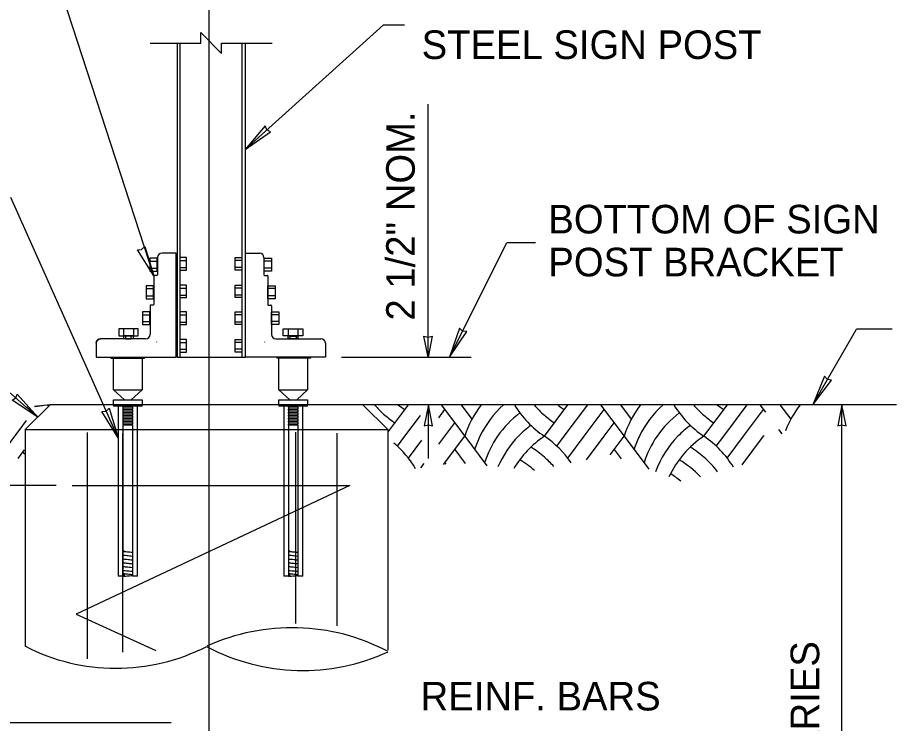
# Model space of a CAD drawing. Extents: x 99862 to 103151, y 102600 to 104676.
# Drawn here: x 100237.1 to 100728.9, y 103776.3 to 104171.1 of the extents above; entities that cross this region are included whole.
import ezdxf

# ---------------------------------------------------------------- set-up
doc = ezdxf.new("R2010")
doc.units = 0
for name, color, linetype in [('Level 1', 7, 'Continuous'), ('Level 10', 7, 'Continuous'), ('Level 15', 7, 'Continuous'), ('Level 2', 7, 'Continuous'), ('Level 20', 7, 'Continuous'), ('Level 5', 7, 'Continuous'), ('Level 6', 7, 'Continuous')]:
    doc.layers.add(name, color=color, linetype=linetype)

msp = doc.modelspace()

# ---------------------------------------------------------------- linework, layer by layer
at = {"layer": 'Level 1'}
for p, q in [((100241.42, 103940.62), (100255.34, 103954.53)), ((100444.29, 103940.62), (100430.37, 103954.53)), ((100241.42, 103940.62), (100444.29, 103940.62))]:
    msp.add_line(p, q, dxfattribs=at)
for points in [[(100430.37, 103954.53), (100255.34, 103954.53)], [(100241.42, 103940.62), (100241.42, 103819.28)], [(100444.29, 103940.62), (100444.29, 103817.34)]]:
    msp.add_lwpolyline(points, dxfattribs=at)
for centre, start, end in [((100390.7, 103714.83), 62.311, 114.5007), ((100396.71, 103920.95), 242.311, 294.5007)]:
    msp.add_arc(centre, 115.01, start, end, dxfattribs=at)
msp.add_ellipse((100294.41, 103921.53), major_axis=(-53.44, -101.84), ratio=0.974778, start_param=0.004573, end_param=0.939153, dxfattribs=at)
at = {"layer": 'Level 10'}
for p, q in [((100276.09, 103938.97), (100276.09, 103812.43)), ((100295.87, 103938.4), (100295.87, 103816.15)), ((100344.39, 103820.92), (100344.39, 103938.75)), ((100392.83, 103832.19), (100392.83, 103939.25)), ((100416.02, 103830.84), (100416.02, 103938.59)), ((100267.68, 103909.42), (100423.11, 103909.42)), ((100423.11, 103909.42), (100269.83, 103837.34)), ((100269.83, 103837.34), (100314.4, 103817.19))]:
    msp.add_line(p, q, dxfattribs=at)
at = {"layer": 'Level 15'}
for p, q in [((100313.33, 104026.58), (100239.9, 104252.06)), ((100344.07, 104241.59), (100344.07, 103359.1)), ((100364.36, 104097.36), (100441.61, 104166.9)), ((100453.62, 104166.9), (100441.61, 104166.9)), ((100293.37, 103936.03), (100233.37, 104070.54)), ((100478.83, 103981.12), (100510.95, 104045.18)), ((100526.97, 104045.18), (100510.95, 104045.18)), ((100682.09, 103954.53), (100706.5, 103996.8)), ((100726.5, 103996.8), (100706.5, 103996.8)), ((100241.92, 103953.22), (100196.88, 103992.57)), ((100418.34, 103981.12), (100490.84, 103981.12)), ((100241.93, 103953.21), (100241.92, 103953.22)), ((100242.09, 103953.06), (100241.93, 103953.21)), ((100242.23, 103952.94), (100242.09, 103953.06)), ((100248.38, 103947.57), (100242.23, 103952.94))]:
    msp.add_line(p, q, dxfattribs=at)
for points in [[(100311.29, 104156.86), (100339.62, 104156.86), (100339.62, 104162.67), (100351.26, 104151.04), (100351.26, 104156.86), (100379.59, 104156.86)], [(100466.81, 103981.12), (100466.81, 104122.66)], [(100466.97, 103924.44), (100466.97, 103954.53)], [(100698.43, 103391.74), (100698.43, 103954.53)], [(100258.67, 103909.42), (100099.21, 103909.42)], [(100201.02, 103776.83), (100322.97, 103776.83)]]:
    msp.add_lwpolyline(points, dxfattribs=at)
for points in [[(100364.36, 104097.36), (100378.6, 104107.17), (100376.51, 104108.3), (100375.6, 104110.5)], [(100313.33, 104026.58), (100304.14, 104041.23), (100306.51, 104041.44), (100308.22, 104043.1)], [(100478.83, 103981.12), (100488.47, 103995.47), (100486.11, 103995.76), (100484.46, 103997.47)], [(100466.81, 103981.12), (100464.49, 103992.93), (100466.81, 103992.38), (100469.13, 103992.93)], [(100682.09, 103954.53), (100692.61, 103968.25), (100690.27, 103968.69), (100688.72, 103970.5)], [(100248.38, 103947.57), (100233.99, 103957.17), (100236.07, 103958.33), (100236.94, 103960.54)], [(100293.37, 103936.03), (100284.31, 103950.76), (100286.68, 103950.95), (100288.4, 103952.59)], [(100466.97, 103954.53), (100464.65, 103942.72), (100466.97, 103943.26), (100469.29, 103942.72)], [(100698.43, 103954.53), (100696.12, 103942.72), (100698.43, 103943.26), (100700.75, 103942.72)]]:
    msp.add_lwpolyline(points, close=True, dxfattribs=at)
at = {"layer": 'Level 2'}
for p, q in [((100327.93, 104156.86), (100327.93, 103981.12)), ((100290.77, 103962.95), (100290.77, 103981.12)), ((100306.83, 103981.12), (100306.83, 103962.95)), ((100383.36, 103962.95), (100383.36, 103981.12)), ((100399.42, 103981.12), (100399.42, 103962.95)), ((100290.78, 103954.47), (100290.78, 103953.68)), ((100306.74, 103954.47), (100290.78, 103954.47)), ((100306.74, 103953.68), (100290.78, 103953.68)), ((100293.41, 103953.68), (100293.41, 103858.72)), ((100296.18, 103953.28), (100296.18, 103953.68)), ((100301.34, 103953.28), (100296.18, 103953.28)), ((100301.34, 103952), (100296.18, 103952)), ((100296.18, 103951.6), (100296.18, 103952)), ((100301.34, 103951.6), (100296.18, 103951.6)), ((100301.34, 103950.32), (100296.18, 103950.32)), ((100296.18, 103949.92), (100296.18, 103950.32)), ((100296.21, 103952), (100296.21, 103953.28)), ((100296.21, 103950.32), (100296.21, 103951.6)), ((100301.31, 103953.28), (100301.31, 103952)), ((100301.31, 103951.6), (100301.31, 103950.32)), ((100301.34, 103953.28), (100301.34, 103953.68)), ((100301.34, 103951.6), (100301.34, 103952)), ((100301.34, 103949.92), (100301.34, 103950.32)), ((100304.11, 103858.72), (100304.11, 103953.68)), ((100306.74, 103953.68), (100306.74, 103954.47)), ((100383.37, 103954.47), (100383.37, 103953.68)), ((100399.33, 103954.47), (100383.37, 103954.47)), ((100399.33, 103953.68), (100383.37, 103953.68)), ((100386, 103953.68), (100386, 103858.72)), ((100388.77, 103953.28), (100388.77, 103953.68)), ((100393.93, 103953.28), (100388.77, 103953.28)), ((100393.93, 103952), (100388.77, 103952)), ((100388.77, 103951.6), (100388.77, 103952)), ((100393.93, 103951.6), (100388.77, 103951.6)), ((100393.93, 103950.32), (100388.77, 103950.32)), ((100388.77, 103949.92), (100388.77, 103950.32)), ((100388.8, 103952), (100388.8, 103953.28)), ((100388.8, 103950.32), (100388.8, 103951.6)), ((100393.9, 103953.28), (100393.9, 103952)), ((100393.9, 103951.6), (100393.9, 103950.32)), ((100393.93, 103953.28), (100393.93, 103953.68)), ((100393.93, 103951.6), (100393.93, 103952)), ((100393.93, 103949.92), (100393.93, 103950.32)), ((100396.7, 103858.72), (100396.7, 103953.68)), ((100399.33, 103953.68), (100399.33, 103954.47)), ((100301.34, 103949.92), (100296.18, 103949.92)), ((100301.34, 103948.65), (100296.18, 103948.65)), ((100296.18, 103948.24), (100296.18, 103948.65)), ((100301.34, 103948.24), (100296.18, 103948.24)), ((100301.34, 103946.97), (100296.18, 103946.97)), ((100296.18, 103946.57), (100296.18, 103946.97)), ((100301.34, 103946.57), (100296.18, 103946.57)), ((100296.21, 103948.65), (100296.21, 103949.92)), ((100296.21, 103946.97), (100296.21, 103948.24)), ((100296.21, 103945.29), (100296.21, 103946.57)), ((100301.31, 103949.92), (100301.31, 103948.65)), ((100301.31, 103948.24), (100301.31, 103946.97)), ((100301.31, 103946.57), (100301.31, 103945.29)), ((100301.34, 103948.24), (100301.34, 103948.65)), ((100301.34, 103946.57), (100301.34, 103946.97)), ((100393.93, 103949.92), (100388.77, 103949.92)), ((100393.93, 103948.65), (100388.77, 103948.65)), ((100388.77, 103948.24), (100388.77, 103948.65)), ((100393.93, 103948.24), (100388.77, 103948.24)), ((100393.93, 103946.97), (100388.77, 103946.97)), ((100388.77, 103946.57), (100388.77, 103946.97)), ((100393.93, 103946.57), (100388.77, 103946.57)), ((100388.8, 103948.65), (100388.8, 103949.92)), ((100388.8, 103946.97), (100388.8, 103948.24)), ((100388.8, 103945.29), (100388.8, 103946.57)), ((100393.9, 103949.92), (100393.9, 103948.65)), ((100393.9, 103948.24), (100393.9, 103946.97)), ((100393.9, 103946.57), (100393.9, 103945.29)), ((100393.93, 103948.24), (100393.93, 103948.65)), ((100393.93, 103946.57), (100393.93, 103946.97)), ((100301.34, 103945.29), (100296.18, 103945.29)), ((100296.18, 103944.89), (100296.18, 103945.29)), ((100301.34, 103944.89), (100296.18, 103944.89)), ((100301.34, 103943.61), (100296.18, 103943.61)), ((100296.18, 103943.21), (100296.18, 103943.61)), ((100301.34, 103943.21), (100296.18, 103943.21)), ((100296.21, 103943.61), (100296.21, 103944.89)), ((100296.21, 103858.72), (100296.21, 103943.21)), ((100301.31, 103944.89), (100301.31, 103943.61)), ((100301.31, 103943.21), (100301.31, 103858.72)), ((100301.34, 103944.89), (100301.34, 103945.29)), ((100301.34, 103943.21), (100301.34, 103943.61)), ((100393.93, 103945.29), (100388.77, 103945.29)), ((100388.77, 103944.89), (100388.77, 103945.29)), ((100393.93, 103944.89), (100388.77, 103944.89)), ((100393.93, 103943.61), (100388.77, 103943.61)), ((100388.77, 103943.21), (100388.77, 103943.61)), ((100393.93, 103943.21), (100388.77, 103943.21)), ((100388.8, 103943.61), (100388.8, 103944.89)), ((100388.8, 103858.72), (100388.8, 103943.21)), ((100393.9, 103944.89), (100393.9, 103943.61)), ((100393.9, 103943.21), (100393.9, 103858.72)), ((100393.93, 103944.89), (100393.93, 103945.29)), ((100393.93, 103943.21), (100393.93, 103943.61)), ((100293.82, 103858.72), (100293.41, 103858.72)), ((100296.21, 103858.72), (100293.82, 103858.72)), ((100303.7, 103858.72), (100301.31, 103858.72)), ((100304.11, 103858.72), (100303.7, 103858.72)), ((100386.41, 103858.72), (100386, 103858.72)), ((100388.8, 103858.72), (100386.41, 103858.72)), ((100396.29, 103858.72), (100393.9, 103858.72)), ((100396.7, 103858.72), (100396.29, 103858.72))]:
    msp.add_line(p, q, dxfattribs=at)
for points in [[(100326.31, 103981.12), (100364.57, 103981.12), (100364.57, 104156.86)], [(100326.31, 104156.86), (100326.31, 103981.12)], [(100362.86, 103981.12), (100362.86, 104156.86)], [(100311.13, 104034.91), (100315.23, 104034.91)], [(100327.87, 104035.24), (100331.63, 104035.24)], [(100362.52, 104035.24), (100358.76, 104035.24)], [(100379.26, 104034.91), (100375.16, 104034.91)], [(100311.13, 104030.89), (100315.23, 104030.89)], [(100327.87, 104031.23), (100331.63, 104031.23)], [(100362.52, 104031.23), (100358.76, 104031.23)], [(100379.26, 104030.89), (100375.16, 104030.89)], [(100309.13, 104019.48), (100313.23, 104019.48)], [(100327.87, 104019.81), (100331.63, 104019.81)], [(100362.52, 104019.81), (100358.76, 104019.81)], [(100381.27, 104019.48), (100377.17, 104019.48)], [(100309.13, 104015.46), (100313.23, 104015.46)], [(100327.87, 104015.8), (100331.63, 104015.8)], [(100362.52, 104015.8), (100358.76, 104015.8)], [(100381.27, 104015.46), (100377.17, 104015.46)], [(100307.07, 104004.79), (100311.17, 104004.79)], [(100327.87, 104004.79), (100331.63, 104004.79)], [(100362.52, 104004.79), (100358.76, 104004.79)], [(100383.33, 104004.79), (100379.23, 104004.79)], [(100307.07, 104001.11), (100311.17, 104001.11)], [(100327.87, 104000.77), (100331.63, 104000.77)], [(100362.52, 104000.77), (100358.76, 104000.77)], [(100383.33, 104001.11), (100379.23, 104001.11)], [(100296.44, 103996.96), (100296.44, 103993.09)], [(100301.91, 103996.96), (100301.91, 103993.09)], [(100388.49, 103996.96), (100388.49, 103993.09)], [(100393.95, 103996.96), (100393.95, 103993.09)], [(100300.68, 103991.55), (100301.91, 103991.55), (100301.91, 103993.09), (100296.44, 103993.09), (100296.44, 103991.55), (100297.45, 103991.55)], [(100389.71, 103991.55), (100388.49, 103991.55), (100388.49, 103993.09), (100393.96, 103993.09), (100393.96, 103991.55), (100392.95, 103991.55)], [(100327.87, 103989.35), (100331.63, 103989.35)], [(100327.87, 103985.67), (100331.63, 103985.67)], [(100362.52, 103989.35), (100358.76, 103989.35)], [(100362.52, 103985.67), (100358.76, 103985.67)], [(100296.91, 103957.26), (100290.77, 103962.95), (100306.83, 103962.95), (100300.7, 103957.26)], [(100389.49, 103957.26), (100383.36, 103962.95), (100399.42, 103962.95), (100393.29, 103957.26)]]:
    msp.add_lwpolyline(points, dxfattribs=at)
for points in [[(100315.23, 104036.58), (100311.13, 104036.58), (100311.13, 104029.22), (100315.23, 104029.22)], [(100331.63, 104036.91), (100327.87, 104036.91), (100327.87, 104029.89), (100331.63, 104029.89)], [(100358.76, 104036.91), (100362.52, 104036.91), (100362.52, 104029.89), (100358.76, 104029.89)], [(100375.16, 104036.58), (100379.26, 104036.58), (100379.26, 104029.22), (100375.16, 104029.22)], [(100313.23, 104021.15), (100309.13, 104021.15), (100309.13, 104013.79), (100313.23, 104013.79)], [(100331.63, 104021.48), (100327.87, 104021.48), (100327.87, 104014.46), (100331.63, 104014.46)], [(100358.76, 104021.48), (100362.52, 104021.48), (100362.52, 104014.46), (100358.76, 104014.46)], [(100377.17, 104021.15), (100381.27, 104021.15), (100381.27, 104013.79), (100377.17, 104013.79)], [(100311.17, 104006.46), (100307.07, 104006.46), (100307.07, 103999.43), (100311.17, 103999.43)], [(100331.63, 104006.46), (100327.87, 104006.46), (100327.87, 103999.43), (100331.63, 103999.43)], [(100358.76, 104006.46), (100362.52, 104006.46), (100362.52, 103999.43), (100358.76, 103999.43)], [(100379.23, 104006.46), (100383.33, 104006.46), (100383.33, 103999.43), (100379.23, 103999.43)], [(100304.64, 103996.96), (100293.71, 103996.96), (100293.71, 103993.09), (100304.64, 103993.09)], [(100385.76, 103996.96), (100396.69, 103996.96), (100396.69, 103993.09), (100385.76, 103993.09)], [(100300.68, 103993), (100297.45, 103993), (100297.45, 103991.46), (100300.68, 103991.46)], [(100331.63, 103991.02), (100327.87, 103991.02), (100327.87, 103984), (100331.63, 103984)], [(100358.76, 103991.02), (100362.52, 103991.02), (100362.52, 103984), (100358.76, 103984)], [(100389.71, 103993), (100392.95, 103993), (100392.95, 103991.46), (100389.71, 103991.46)], [(100308.13, 103981), (100289.31, 103981), (100289.31, 103980.58), (100308.13, 103980.58)], [(100382.27, 103981), (100401.08, 103981), (100401.08, 103980.58), (100382.27, 103980.58)], [(100290.77, 103957.26), (100306.83, 103957.26), (100306.83, 103954.59), (100290.77, 103954.59)], [(100383.36, 103957.26), (100399.42, 103957.26), (100399.42, 103954.59), (100383.36, 103954.59)]]:
    msp.add_lwpolyline(points, close=True, dxfattribs=at)
for centre, ratio, start_param, end_param in [((100296.32, 103872.13), 0.703573, 1.740072, 3.144905), ((100388.91, 103872.13), 0.703573, 1.740072, 3.144905), ((100296.32, 103859.36), 0.703842, 5.555756, 6.285821), ((100296.32, 103859.36), 0.703842, 1.475078, 3.14378), ((100296.32, 103859.36), 0.703842, 0.002636, 1.475078), ((100388.91, 103859.36), 0.703842, 5.555756, 6.285821), ((100388.91, 103859.36), 0.703842, 1.475078, 3.14378), ((100388.91, 103859.36), 0.703842, 0.002636, 1.475078)]:
    msp.add_ellipse(centre, major_axis=(0.108, -0.791), ratio=ratio, start_param=start_param, end_param=end_param, dxfattribs=at)
for points, degree in [([(100296.21, 103872.92), (100296.21, 103872.92), (100296.21, 103872.92), (100296.21, 103872.92)], 2), ([(100301.31, 103871.85), (100300.39, 103871.98), (100298.28, 103872.17), (100296.59, 103872.36), (100296.21, 103872.41)], 3), ([(100388.8, 103872.92), (100388.8, 103872.92), (100388.8, 103872.92), (100388.8, 103872.92)], 2), ([(100393.9, 103871.85), (100392.98, 103871.98), (100390.87, 103872.17), (100389.18, 103872.36), (100388.8, 103872.41)], 3), ([(100301.31, 103869.73), (100300.19, 103869.89), (100298.02, 103870.06), (100296.57, 103870.25), (100296.33, 103870.29), (100296.21, 103870.31)], 3), ([(100301.31, 103867.61), (100300.91, 103867.66), (100299.19, 103867.83), (100296.97, 103868.06), (100296.21, 103868.16)], 3), ([(100393.9, 103869.73), (100392.78, 103869.89), (100390.61, 103870.06), (100389.16, 103870.25), (100388.92, 103870.29), (100388.8, 103870.31)], 3), ([(100393.9, 103867.61), (100393.5, 103867.66), (100391.78, 103867.83), (100389.56, 103868.06), (100388.8, 103868.16)], 3), ([(100301.31, 103865.47), (100301.24, 103865.48), (100299.87, 103865.67), (100297.37, 103865.86), (100296.26, 103866.04), (100296.21, 103866.05)], 3), ([(100301.31, 103863.35), (100300.18, 103863.5), (100297.91, 103863.69), (100296.46, 103863.88), (100296.21, 103863.92)], 3), ([(100301.31, 103861.21), (100300.09, 103861.38), (100297.67, 103861.58), (100296.37, 103861.76), (100296.23, 103861.78), (100296.21, 103861.79)], 3), ([(100393.9, 103865.47), (100393.83, 103865.48), (100392.46, 103865.67), (100389.95, 103865.86), (100388.85, 103866.04), (100388.8, 103866.05)], 3), ([(100393.9, 103863.35), (100392.77, 103863.5), (100390.5, 103863.69), (100389.05, 103863.88), (100388.8, 103863.92)], 3), ([(100393.9, 103861.21), (100392.68, 103861.38), (100390.25, 103861.58), (100388.96, 103861.76), (100388.82, 103861.78), (100388.8, 103861.79)], 3), ([(100296.21, 103860.18), (100296.34, 103860.16), (100296.6, 103860.13), (100297.78, 103859.96), (100299.41, 103859.84), (100300.66, 103859.68), (100301.05, 103859.63), (100301.25, 103859.6), (100301.31, 103859.59)], 3), ([(100296.43, 103858.57), (100296.53, 103858.58), (100296.72, 103858.61), (100298.23, 103858.78), (100300.15, 103858.94), (100301.31, 103859.09)], 3), ([(100388.8, 103860.18), (100388.93, 103860.16), (100389.19, 103860.13), (100390.36, 103859.96), (100392, 103859.84), (100393.25, 103859.68), (100393.64, 103859.63), (100393.84, 103859.6), (100393.9, 103859.59)], 3), ([(100389.01, 103858.57), (100389.11, 103858.58), (100389.31, 103858.61), (100390.82, 103858.78), (100392.73, 103858.94), (100393.9, 103859.09)], 3)]:
    msp.add_open_spline(points, degree=degree, dxfattribs=at)
at = {"layer": 'Level 5'}
for p, q in [((100255.34, 103954.53), (100246.53, 103953.56)), ((100246.69, 103953.57), (100250.94, 103954.04)), ((100253.75, 103954.35), (100254.35, 103953.54)), ((100444.72, 103939.67), (100455.87, 103954.53)), ((100472.74, 103947.29), (100476.15, 103951.82)), ((100474.12, 103954.53), (100487.3, 103936.95)), ((100485.27, 103954.53), (100491.32, 103946.47)), ((100496.42, 103954.53), (100496.49, 103954.44)), ((100531.91, 103936.95), (100545.09, 103954.53)), ((100543.06, 103936.95), (100556.24, 103954.53)), ((100554.21, 103936.95), (100565.36, 103951.82)), ((100563.34, 103954.53), (100576.52, 103936.95)), ((100574.49, 103954.53), (100580.53, 103946.47)), ((100585.64, 103954.53), (100585.71, 103954.44)), ((100621.13, 103936.95), (100634.31, 103954.53)), ((100632.28, 103936.95), (100645.46, 103954.53)), ((100643.43, 103936.95), (100654.58, 103951.82)), ((100652.56, 103954.53), (100655.65, 103950.4)), ((100663.71, 103954.53), (100669.75, 103946.47)), ((100674.86, 103954.53), (100674.93, 103954.44)), ((100240.05, 103942.88), (100242.15, 103945.68)), ((100453.84, 103936.95), (100462.48, 103948.47)), ((100228.63, 103927.65), (100240.05, 103942.88)), ((100476.15, 103936.95), (100481.72, 103944.39)), ((100565.36, 103936.95), (100570.94, 103944.39)), ((100662.89, 103940.75), (100664.75, 103938.26)), ((100449.68, 103931.4), (100453.84, 103936.95)), ((100472.79, 103932.48), (100476.15, 103936.95)), ((100475.43, 103921.12), (100487.3, 103936.95)), ((100487.3, 103936.95), (100499.68, 103920.45)), ((100538.9, 103931.4), (100543.06, 103936.95)), ((100545.02, 103924.7), (100554.21, 103936.95)), ((100555.52, 103923.83), (100565.36, 103936.95)), ((100568.7, 103926.54), (100576.52, 103936.95)), ((100576.52, 103936.95), (100590.37, 103918.48)), ((100628.12, 103931.4), (100632.28, 103936.95)), ((100634.24, 103924.7), (100643.43, 103936.95)), ((100642.64, 103921.03), (100654.58, 103936.95)), ((100654.58, 103936.95), (100654.84, 103937.29)), ((100455.8, 103924.7), (100463.4, 103934.82)), ((100237.36, 103924.43), (100240.98, 103929.25)), ((100240.05, 103928.01), (100240.89, 103926.89)), ((100481.72, 103929.52), (100487.55, 103921.74)), ((100570.94, 103929.52), (100574.91, 103924.23)), ((100462.83, 103919.2), (100464.68, 103921.66)), ((100476.15, 103922.08), (100476.72, 103921.32))]:
    msp.add_line(p, q, dxfattribs=at)
msp.add_lwpolyline([(100728.92, 103954.53), (100430.37, 103954.53)], dxfattribs=at)
for centre, start, end in [((100479.75, 103991.23), 220.5665, 228.9599), ((100485.33, 103998.67), 231.4488, 236.0964), ((100541.09, 103919.84), 142.0873, 162.3566), ((100546.66, 103912.41), 131.7393, 154.2266), ((100563.39, 103983.8), 211.239, 236.0964), ((100568.97, 103991.23), 220.5665, 228.9599), ((100574.54, 103998.67), 231.4488, 236.0964), ((100630.31, 103919.84), 142.0873, 162.3566), ((100635.88, 103912.41), 131.7393, 154.2266), ((100652.61, 103983.8), 211.239, 236.0964), ((100658.19, 103991.23), 220.5665, 228.9599), ((100663.76, 103998.67), 231.4488, 236.0964), ((100719.53, 103919.84), 142.0873, 159.0693), ((100479.75, 103991.23), 228.9599, 236.0964), ((100552.24, 103904.97), 127.1006, 145.4911), ((100568.97, 103991.23), 228.9599, 236.0964), ((100641.46, 103904.97), 127.1006, 145.4911), ((100658.19, 103991.23), 228.9599, 236.0964), ((100557.82, 103897.54), 126.331, 135.7128), ((100647.04, 103897.54), 126.331, 135.7128), ((100546.66, 103912.41), 154.2265, 162.3566), ((100552.24, 103904.97), 145.491, 162.3566), ((100557.82, 103897.54), 135.7127, 156.7978), ((100563.39, 103890.1), 123.9036, 149.4093), ((100500.42, 103890.1), 34.4434, 56.0963), ((100635.88, 103912.41), 154.2265, 162.3566), ((100641.46, 103904.97), 145.491, 162.3566), ((100647.04, 103897.54), 135.7127, 159.729), ((100652.61, 103890.1), 123.9036, 154.6223), ((100589.64, 103890.1), 31.526, 56.0963), ((100411.2, 103890.1), 30.4844, 49.6595), ((100494.85, 103882.67), 48.9597, 58.5465), ((100584.07, 103882.67), 48.9597, 58.5465), ((100489.27, 103875.23), 48.8121, 59.3021), ((100494.85, 103882.67), 41.3709, 48.9597), ((100578.49, 103875.23), 43.7622, 59.3021), ((100584.07, 103882.67), 37.5154, 48.9597), ((100572.91, 103867.8), 51.2805, 58.4874)]:
    msp.add_arc(centre, 56.44, start, end, dxfattribs=at)
at = {"layer": 'Level 6'}
for p, q in [((100315.41, 104036.91), (100315.41, 104027.25)), ((100374.98, 104036.91), (100374.98, 104027.25)), ((100313.33, 104026.58), (100313.33, 104010.59)), ((100313.67, 104026.92), (100313.54, 104026.89)), ((100315.08, 104026.92), (100313.67, 104026.92)), ((100375.31, 104026.92), (100376.73, 104026.92)), ((100376.73, 104026.92), (100376.86, 104026.89)), ((100377.06, 104026.58), (100377.06, 104010.59)), ((100311.25, 104009.93), (100311.25, 103993.93)), ((100313, 104010.26), (100311.58, 104010.26)), ((100377.4, 104010.26), (100378.81, 104010.26)), ((100379.14, 104009.93), (100379.14, 103993.93)), ((100281.8, 103990.7), (100282.61, 103991.24)), ((100282.61, 103991.24), (100283.56, 103991.43)), ((100308.75, 103991.43), (100283.56, 103991.43)), ((100315, 103989.53), (100315, 103989.7)), ((100375.4, 103989.53), (100375.4, 103989.7)), ((100381.64, 103991.43), (100406.83, 103991.43)), ((100407.79, 103991.24), (100406.83, 103991.43)), ((100408.6, 103990.7), (100407.79, 103991.24))]:
    msp.add_line(p, q, dxfattribs=at)
for points in [[(100325.82, 103981.12), (100325.82, 104039.41), (100317.91, 104039.41)], [(100364.57, 103981.12), (100364.57, 104039.41), (100372.48, 104039.41)], [(100313.54, 104026.89), (100313.43, 104026.82), (100313.36, 104026.71), (100313.33, 104026.58)], [(100376.86, 104026.89), (100376.97, 104026.82), (100377.04, 104026.71), (100377.06, 104026.58)], [(100281.07, 103988.93), (100281.26, 103989.89), (100281.8, 103990.7)], [(100409.33, 103988.93), (100409.14, 103989.89), (100408.6, 103990.7)], [(100281.07, 103988.93), (100281.07, 103981.12), (100281.07, 103981.12)], [(100409.33, 103988.93), (100409.33, 103981.12), (100409.33, 103981.12)], [(100281.07, 103981.12), (100325.82, 103981.12), (100325.82, 103981.12)], [(100409.33, 103981.12), (100364.57, 103981.12), (100364.57, 103981.12)]]:
    msp.add_lwpolyline(points, dxfattribs=at)
for centre, radius, start, end in [((100317.91, 104036.91), 2.5, 90, 180), ((100372.48, 104036.91), 2.5, 0, 90), ((100313.67, 104026.58), 0.333, 90, 180), ((100315.08, 104027.25), 0.333, 270, 0), ((100375.31, 104027.25), 0.333, 180, 270), ((100376.73, 104026.58), 0.333, 0, 90), ((100311.58, 104009.93), 0.333, 90, 180), ((100313, 104010.59), 0.333, 270, 0), ((100377.4, 104010.59), 0.333, 180, 270), ((100378.81, 104009.93), 0.333, 360, 90), ((100283.56, 103988.93), 2.5, 90, 180), ((100308.75, 103993.93), 2.5, 270, 0), ((100381.64, 103993.93), 2.5, 180, 270), ((100406.83, 103988.93), 2.5, 0, 90)]:
    msp.add_arc(centre, radius, start, end, dxfattribs=at)

# ---------------------------------------------------------------- texts
at = {"layer": 'Level 20'}
for s, rotation, p in [('STEEL SIGN POST', 360, (100463.23, 104147.93)), ('2 1/2" NOM.', 90, (100459.37, 104001.63)), ('BOTTOM OF SIGN', 360, (100534.13, 104050.36)), ('POST BRACKET', 360, (100534.13, 104026.36)), ('FOUNDATION DEPTH VARIES', 90, (100685.7, 103517.99)), ('REINF. BARS', 360, (100462.65, 103783.56))]:
    msp.add_text(s, height=16, rotation=rotation, dxfattribs=at).set_placement(p)

doc.saveas('drawing.dxf')
